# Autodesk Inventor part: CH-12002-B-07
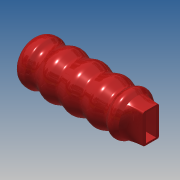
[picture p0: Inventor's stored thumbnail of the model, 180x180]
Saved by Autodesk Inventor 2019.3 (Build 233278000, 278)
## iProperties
Created: 2012-09
Part Number: CH-12002-B-07
Material: Ogólny
Document SubType Name: Modeling
Designer: CADENGINEERING4
Density: 1 g/cm^3
Appearance: Jasnoczerwona
Author: CADENGINEERING4
Revision Number: ÈÎºÎ
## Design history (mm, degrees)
feature "Ô²½Ç11"
node "Bryła1"
